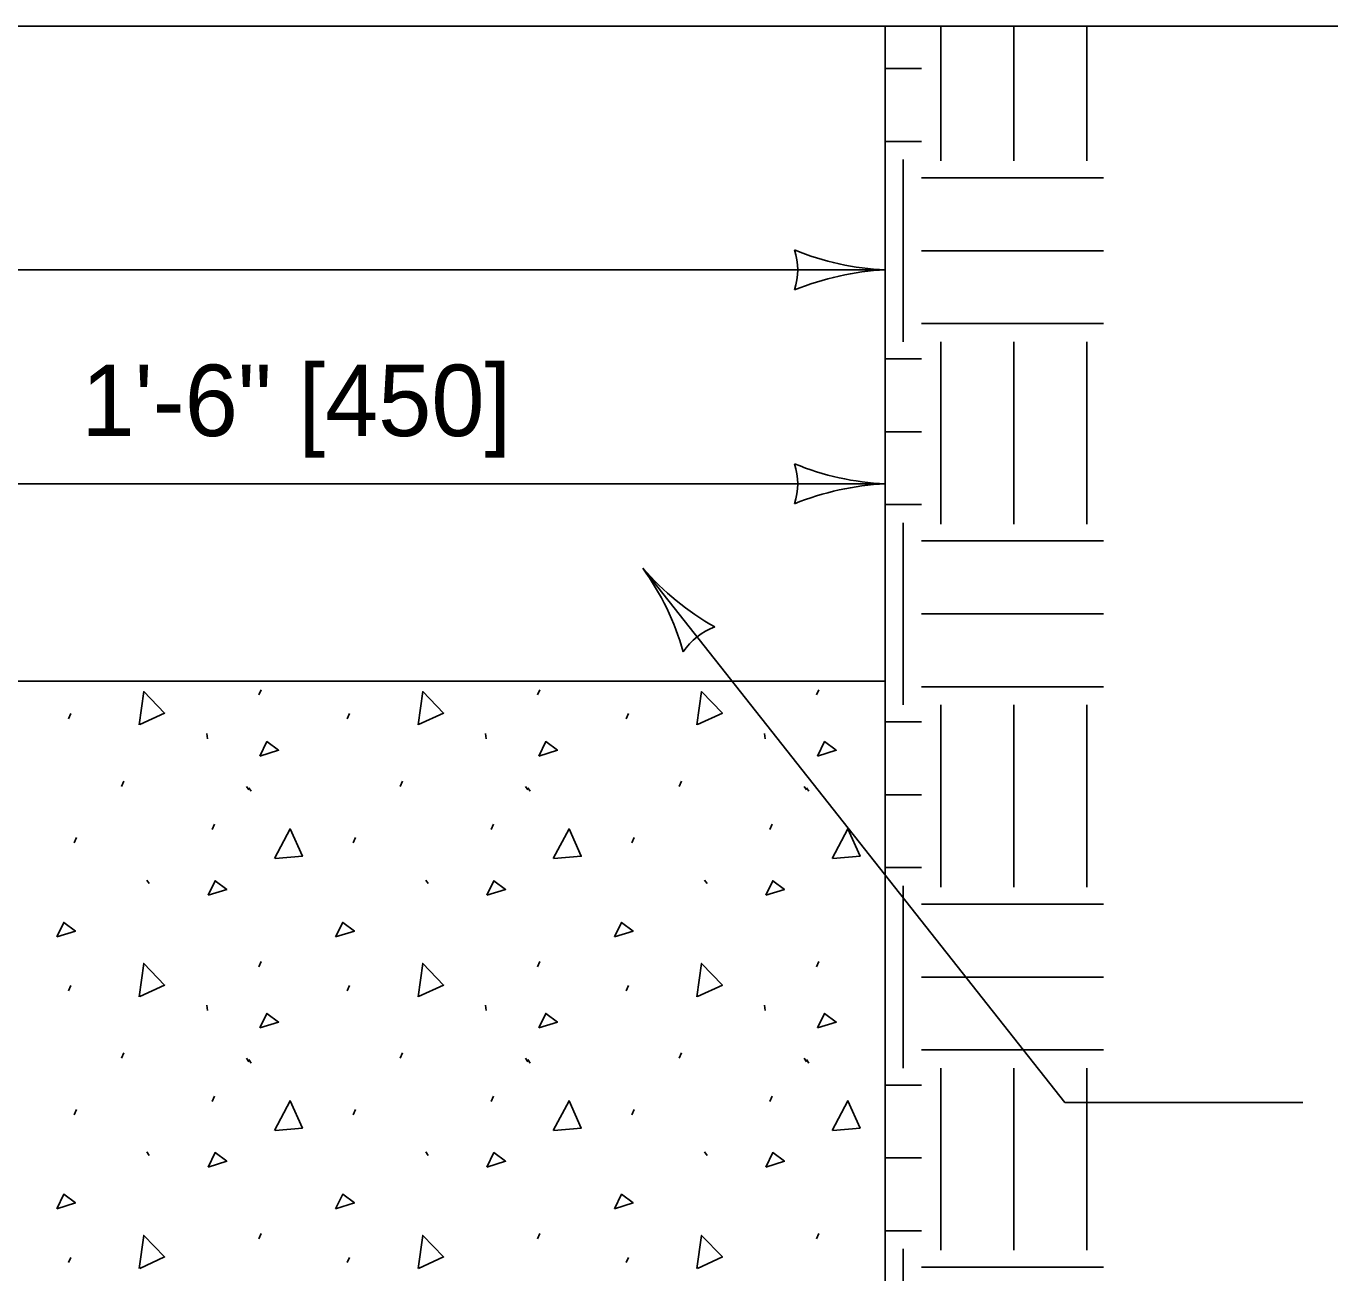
# Model space of a CAD drawing. Extents: x 49991.4 to 50061.4, y 49960.6 to 50011.4.
# Drawn here: x 50014.03 to 50015.124, y 49996.596 to 49997.642 of the extents above; entities that cross this region are included whole.
import ezdxf

# ---------------------------------------------------------------- set-up
doc = ezdxf.new("R2010")
doc.units = 0
for name, color, linetype in [('Level 1', 7, 'Continuous'), ('Level 2', 7, 'Continuous'), ('Level 3', 7, 'Continuous')]:
    doc.layers.add(name, color=color, linetype=linetype)

msp = doc.modelspace()

# ---------------------------------------------------------------- linework, layer by layer
at = {"layer": 'Level 1'}
for p, q in [((50015.4944, 49997.6424), (50011.6711, 49997.6424)), ((50014.7511, 49997.0926), (50014.7511, 49997.6424)), ((50014.7979, 49997.6424), (50014.7979, 49997.5292)), ((50014.859, 49997.6424), (50014.859, 49997.5292)), ((50014.9202, 49997.6424), (50014.9202, 49997.5292)), ((50014.7511, 49997.6067), (50014.7815, 49997.6067)), ((50014.7511, 49997.5455), (50014.7815, 49997.5455)), ((50014.7662, 49997.5303), (50014.7662, 49997.3774)), ((50014.7815, 49997.515), (50014.9343, 49997.515)), ((50014.7815, 49997.4538), (50014.9343, 49997.4538)), ((50014.7815, 49997.3927), (50014.9343, 49997.3927)), ((50014.7979, 49997.3774), (50014.7979, 49997.2245)), ((50014.859, 49997.3774), (50014.859, 49997.2245)), ((50014.9202, 49997.3774), (50014.9202, 49997.2245)), ((50014.7511, 49997.3632), (50014.7815, 49997.3632)), ((50014.7511, 49997.302), (50014.7815, 49997.302)), ((50014.7511, 49997.2408), (50014.7815, 49997.2408)), ((50014.7662, 49997.2256), (50014.7662, 49997.0727)), ((50014.7815, 49997.2103), (50014.9343, 49997.2103)), ((50014.7815, 49997.1491), (50014.9343, 49997.1491)), ((50012.4143, 49997.0926), (50014.7511, 49997.0926)), ((50014.7511, 49997.0926), (50014.7511, 49995.58)), ((50014.7815, 49997.088), (50014.9343, 49997.088)), ((50014.2255, 49997.0811), (50014.2274, 49997.0855)), ((50014.4594, 49997.0811), (50014.4614, 49997.0855)), ((50014.6934, 49997.0811), (50014.6953, 49997.0855)), ((50014.0658, 49997.0611), (50014.0677, 49997.0655)), ((50014.2997, 49997.0611), (50014.3017, 49997.0655)), ((50014.5337, 49997.0611), (50014.5356, 49997.0655)), ((50014.7979, 49997.0727), (50014.7979, 49996.9198)), ((50014.859, 49997.0727), (50014.859, 49996.9198)), ((50014.9202, 49997.0727), (50014.9202, 49996.9198)), ((50014.7511, 49997.0585), (50014.7815, 49997.0585)), ((50014.1819, 49997.0488), (50014.1824, 49997.0444)), ((50014.4158, 49997.0488), (50014.4163, 49997.0444)), ((50014.6498, 49997.0488), (50014.6503, 49997.0444)), ((50014.1102, 49997.0044), (50014.1122, 49997.0088)), ((50014.2152, 49997.0044), (50014.2172, 49997.0015)), ((50014.2172, 49997.0033), (50014.2191, 49997.0004)), ((50014.3442, 49997.0044), (50014.3461, 49997.0088)), ((50014.4492, 49997.0044), (50014.4511, 49997.0015)), ((50014.4511, 49997.0033), (50014.4531, 49997.0004)), ((50014.5781, 49997.0044), (50014.5801, 49997.0088)), ((50014.6831, 49997.0044), (50014.6851, 49997.0015)), ((50014.6851, 49997.0033), (50014.687, 49997.0004)), ((50014.7511, 49996.9973), (50014.7815, 49996.9973)), ((50014.1864, 49996.9682), (50014.1883, 49996.9726)), ((50014.4204, 49996.9682), (50014.4223, 49996.9726)), ((50014.6543, 49996.9682), (50014.6563, 49996.9726)), ((50014.0706, 49996.957), (50014.0726, 49996.9614)), ((50014.3046, 49996.957), (50014.3066, 49996.9614)), ((50014.5386, 49996.957), (50014.5405, 49996.9614)), ((50014.7511, 49996.9362), (50014.7815, 49996.9362)), ((50014.1317, 49996.9257), (50014.1336, 49996.9228)), ((50014.3656, 49996.9257), (50014.3676, 49996.9228)), ((50014.5996, 49996.9257), (50014.6016, 49996.9228)), ((50014.7662, 49996.9209), (50014.7662, 49996.768)), ((50014.7815, 49996.9056), (50014.9343, 49996.9056)), ((50014.2255, 49996.853), (50014.2274, 49996.8573)), ((50014.4594, 49996.853), (50014.4614, 49996.8573)), ((50014.6934, 49996.853), (50014.6953, 49996.8573)), ((50014.0658, 49996.8329), (50014.0677, 49996.8373)), ((50014.2997, 49996.8329), (50014.3017, 49996.8373)), ((50014.5337, 49996.8329), (50014.5356, 49996.8373)), ((50014.7815, 49996.8444), (50014.9343, 49996.8444)), ((50014.1819, 49996.8207), (50014.1824, 49996.8163)), ((50014.4158, 49996.8207), (50014.4163, 49996.8163)), ((50014.6498, 49996.8207), (50014.6503, 49996.8163)), ((50014.1102, 49996.7763), (50014.1122, 49996.7807)), ((50014.3442, 49996.7763), (50014.3461, 49996.7807)), ((50014.5781, 49996.7763), (50014.5801, 49996.7807)), ((50014.7815, 49996.7833), (50014.9343, 49996.7833)), ((50014.2152, 49996.7763), (50014.2172, 49996.7733)), ((50014.2172, 49996.7752), (50014.2191, 49996.7722)), ((50014.4492, 49996.7763), (50014.4511, 49996.7733)), ((50014.4511, 49996.7752), (50014.4531, 49996.7722)), ((50014.6831, 49996.7763), (50014.6851, 49996.7733)), ((50014.6851, 49996.7752), (50014.687, 49996.7722)), ((50014.7979, 49996.768), (50014.7979, 49996.6151)), ((50014.859, 49996.768), (50014.859, 49996.6151)), ((50014.9202, 49996.768), (50014.9202, 49996.6151)), ((50014.7511, 49996.7538), (50014.7815, 49996.7538)), ((50014.1864, 49996.7401), (50014.1883, 49996.7445)), ((50014.4204, 49996.7401), (50014.4223, 49996.7445)), ((50014.6543, 49996.7401), (50014.6563, 49996.7445)), ((50014.0706, 49996.7288), (50014.0726, 49996.7332)), ((50014.3046, 49996.7288), (50014.3066, 49996.7332)), ((50014.5386, 49996.7288), (50014.5405, 49996.7332)), ((50014.1317, 49996.6976), (50014.1336, 49996.6946)), ((50014.3656, 49996.6976), (50014.3676, 49996.6946)), ((50014.5996, 49996.6976), (50014.6016, 49996.6946)), ((50014.7511, 49996.6926), (50014.7815, 49996.6926)), ((50014.2255, 49996.6248), (50014.2274, 49996.6292)), ((50014.4594, 49996.6248), (50014.4614, 49996.6292)), ((50014.6934, 49996.6248), (50014.6953, 49996.6292)), ((50014.7511, 49996.6315), (50014.7815, 49996.6315)), ((50014.7662, 49996.6162), (50014.7662, 49996.4633)), ((50014.0658, 49996.6048), (50014.0677, 49996.6092)), ((50014.2997, 49996.6048), (50014.3017, 49996.6092)), ((50014.5337, 49996.6048), (50014.5356, 49996.6092)), ((50014.7815, 49996.6009), (50014.9343, 49996.6009))]:
    msp.add_line(p, q, dxfattribs=at)
for points in [[(50014.1252, 49997.056), (50014.129, 49997.0839), (50014.1465, 49997.0659), (50014.1256, 49997.0562)], [(50014.3591, 49997.056), (50014.363, 49997.0839), (50014.3805, 49997.0659), (50014.3596, 49997.0562)], [(50014.5931, 49997.056), (50014.597, 49997.0839), (50014.6145, 49997.0659), (50014.5935, 49997.0562)], [(50014.2265, 49997.0298), (50014.2323, 49997.042), (50014.2421, 49997.0347), (50014.2265, 49997.0298)], [(50014.4604, 49997.0298), (50014.4663, 49997.042), (50014.476, 49997.0347), (50014.4604, 49997.0298)], [(50014.6944, 49997.0298), (50014.7002, 49997.042), (50014.71, 49997.0347), (50014.6944, 49997.0298)], [(50014.2387, 49996.9438), (50014.2518, 49996.9687), (50014.2621, 49996.9458), (50014.2392, 49996.9438)], [(50014.4726, 49996.9438), (50014.4858, 49996.9687), (50014.4961, 49996.9458), (50014.4731, 49996.9438)], [(50014.7066, 49996.9438), (50014.7198, 49996.9687), (50014.73, 49996.9458), (50014.7071, 49996.9438)], [(50014.183, 49996.913), (50014.1888, 49996.9252), (50014.1986, 49996.9179), (50014.183, 49996.913)], [(50014.4169, 49996.913), (50014.4228, 49996.9252), (50014.4326, 49996.9179), (50014.4169, 49996.913)], [(50014.6509, 49996.913), (50014.6567, 49996.9252), (50014.6665, 49996.9179), (50014.6509, 49996.913)], [(50014.0561, 49996.8781), (50014.0619, 49996.8903), (50014.0717, 49996.883), (50014.0561, 49996.8781)], [(50014.29, 49996.8781), (50014.2959, 49996.8903), (50014.3057, 49996.883), (50014.29, 49996.8781)], [(50014.524, 49996.8781), (50014.5299, 49996.8903), (50014.5396, 49996.883), (50014.524, 49996.8781)], [(50014.1252, 49996.8279), (50014.129, 49996.8558), (50014.1465, 49996.8377), (50014.1256, 49996.828)], [(50014.3591, 49996.8279), (50014.363, 49996.8558), (50014.3805, 49996.8377), (50014.3596, 49996.828)], [(50014.5931, 49996.8279), (50014.597, 49996.8558), (50014.6145, 49996.8377), (50014.5935, 49996.828)], [(50014.2265, 49996.8017), (50014.2323, 49996.8139), (50014.2421, 49996.8066), (50014.2265, 49996.8017)], [(50014.4604, 49996.8017), (50014.4663, 49996.8139), (50014.476, 49996.8066), (50014.4604, 49996.8017)], [(50014.6944, 49996.8017), (50014.7002, 49996.8139), (50014.71, 49996.8066), (50014.6944, 49996.8017)], [(50014.2387, 49996.7157), (50014.2518, 49996.7406), (50014.2621, 49996.7176), (50014.2392, 49996.7157)], [(50014.4726, 49996.7157), (50014.4858, 49996.7406), (50014.4961, 49996.7176), (50014.4731, 49996.7157)], [(50014.7066, 49996.7157), (50014.7198, 49996.7406), (50014.73, 49996.7176), (50014.7071, 49996.7157)], [(50014.183, 49996.6849), (50014.1888, 49996.6971), (50014.1986, 49996.6898), (50014.183, 49996.6849)], [(50014.4169, 49996.6849), (50014.4228, 49996.6971), (50014.4326, 49996.6898), (50014.4169, 49996.6849)], [(50014.6509, 49996.6849), (50014.6567, 49996.6971), (50014.6665, 49996.6898), (50014.6509, 49996.6849)], [(50014.0561, 49996.65), (50014.0619, 49996.6622), (50014.0717, 49996.6549), (50014.0561, 49996.65)], [(50014.29, 49996.65), (50014.2959, 49996.6622), (50014.3057, 49996.6549), (50014.29, 49996.65)], [(50014.524, 49996.65), (50014.5299, 49996.6622), (50014.5396, 49996.6549), (50014.524, 49996.65)], [(50014.1252, 49996.5997), (50014.129, 49996.6276), (50014.1465, 49996.6096), (50014.1256, 49996.5999)], [(50014.3591, 49996.5997), (50014.363, 49996.6276), (50014.3805, 49996.6096), (50014.3596, 49996.5999)], [(50014.5931, 49996.5997), (50014.597, 49996.6276), (50014.6145, 49996.6096), (50014.5935, 49996.5999)]]:
    msp.add_lwpolyline(points, dxfattribs=at)
at = {"layer": 'Level 3'}
for p, q in [((50012.4143, 49997.4378), (50014.7511, 49997.4378)), ((50014.7511, 49997.2583), (50013.9265, 49997.2583)), ((50014.5477, 49997.1874), (50014.9018, 49996.7392)), ((50015.1014, 49996.7392), (50014.9018, 49996.7392))]:
    msp.add_line(p, q, dxfattribs=at)
for centre, radius, start, end in [((50014.7603, 49997.6599), 0.2223, 247.456, 267.6395), ((50014.6229, 49997.4378), 0.0548, 342.1388, 17.8612), ((50014.7626, 49997.2051), 0.233, 92.8273, 112.0772), ((50014.7603, 49997.4804), 0.2223, 247.456, 267.6395), ((50014.6229, 49997.2583), 0.0548, 342.1388, 17.8612), ((50014.7626, 49997.0256), 0.233, 92.8273, 112.0772), ((50014.3677, 49997.0569), 0.2223, 15.7654, 35.9489), ((50014.7232, 49997.3407), 0.233, 221.1367, 240.3865), ((50014.6272, 49997.0868), 0.0548, 110.4482, 146.1705)]:
    msp.add_arc(centre, radius, start, end, dxfattribs=at)

# ---------------------------------------------------------------- texts
at = {"layer": 'Level 2'}
msp.add_text('1\'-6" [450]', height=0.06, dxfattribs=at).set_placement((50014.0767, 49997.2983))

doc.saveas('drawing.dxf')
